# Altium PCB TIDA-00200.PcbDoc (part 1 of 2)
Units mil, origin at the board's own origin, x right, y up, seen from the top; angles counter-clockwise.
Board outline 5000 x 4400 mil, 2 copper layers (Top Layer, Bottom Layer), stack 62 mil thick; 122 components, 56 nets, 288 pads, 55 vias.
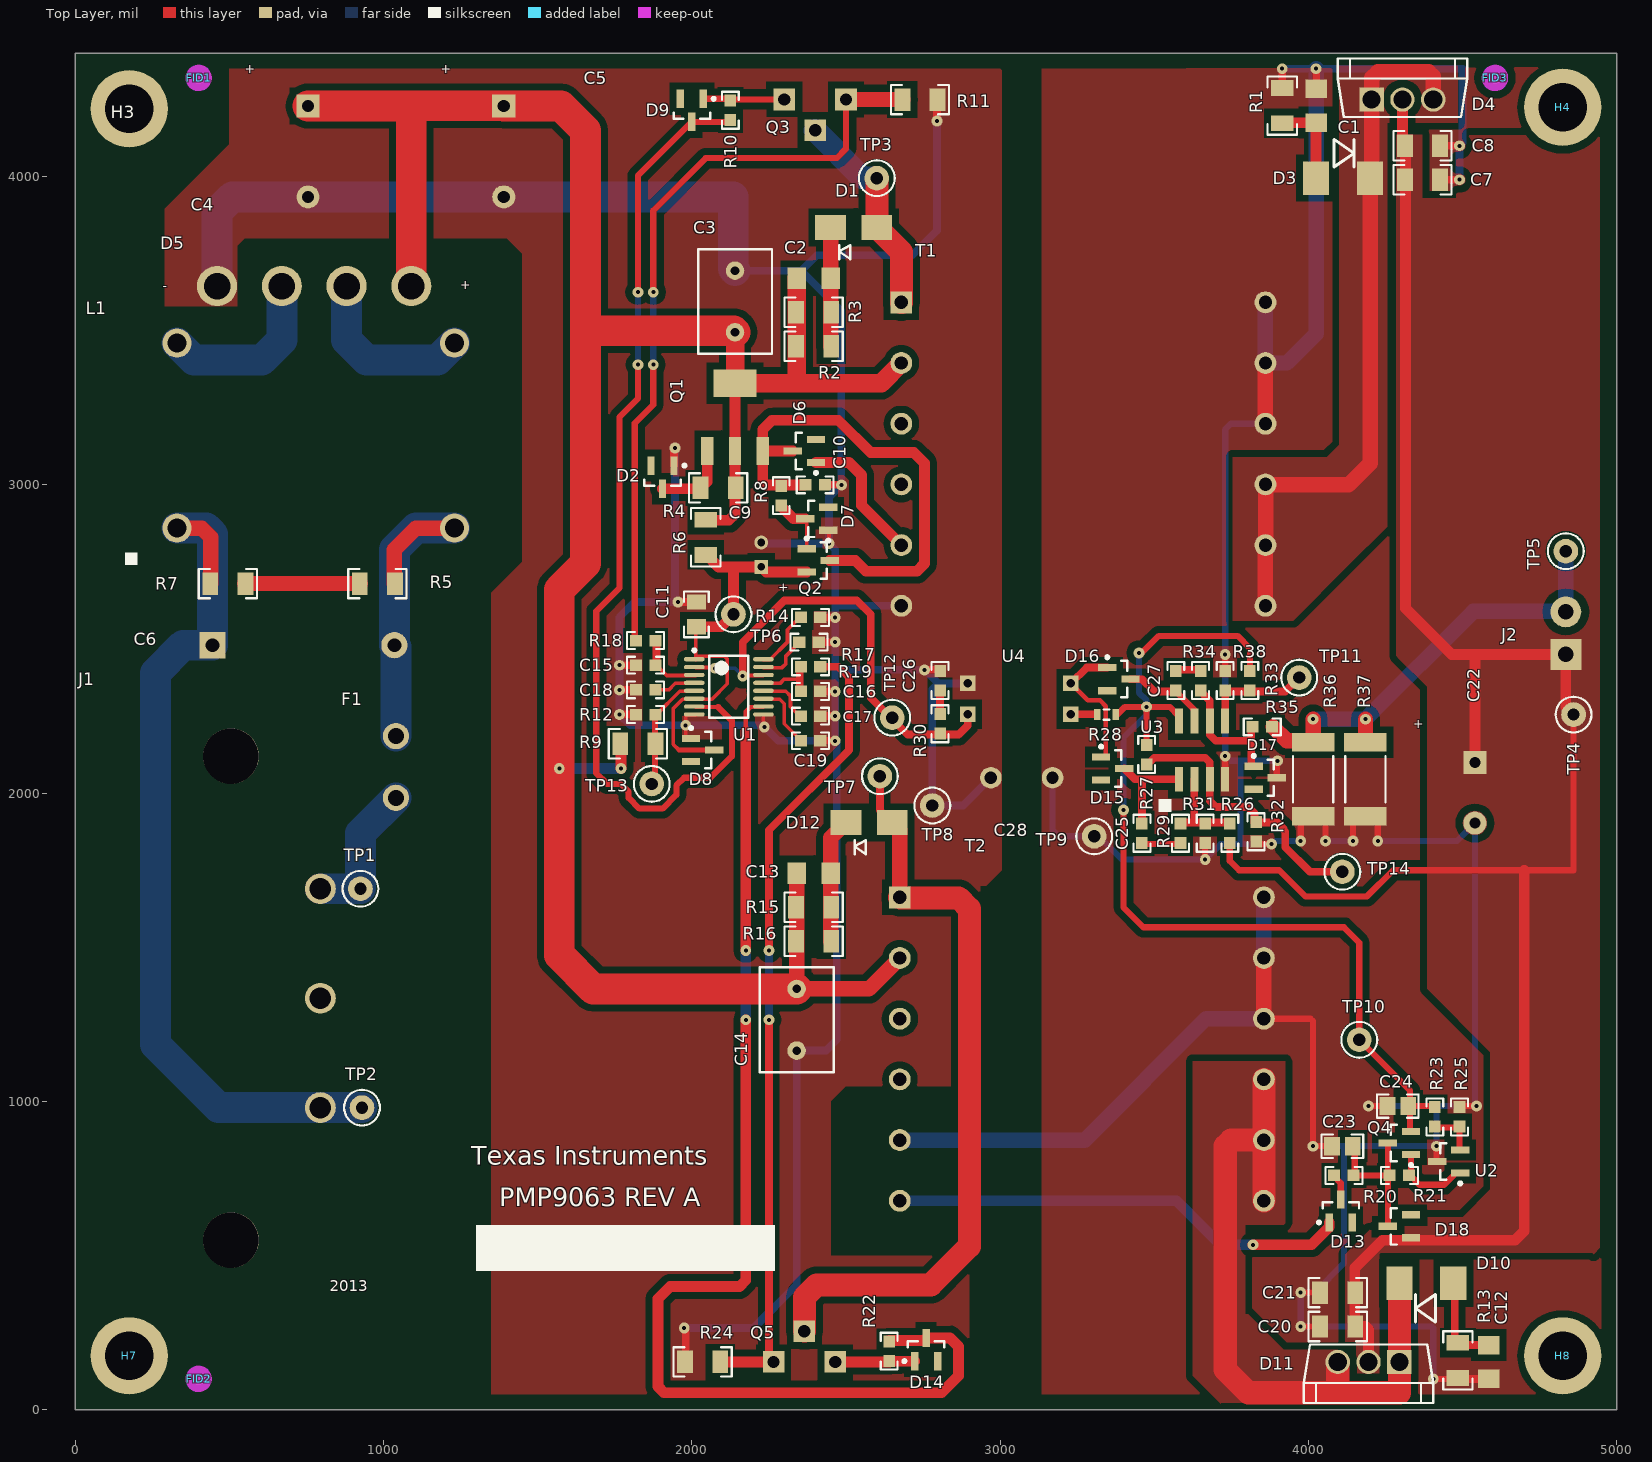
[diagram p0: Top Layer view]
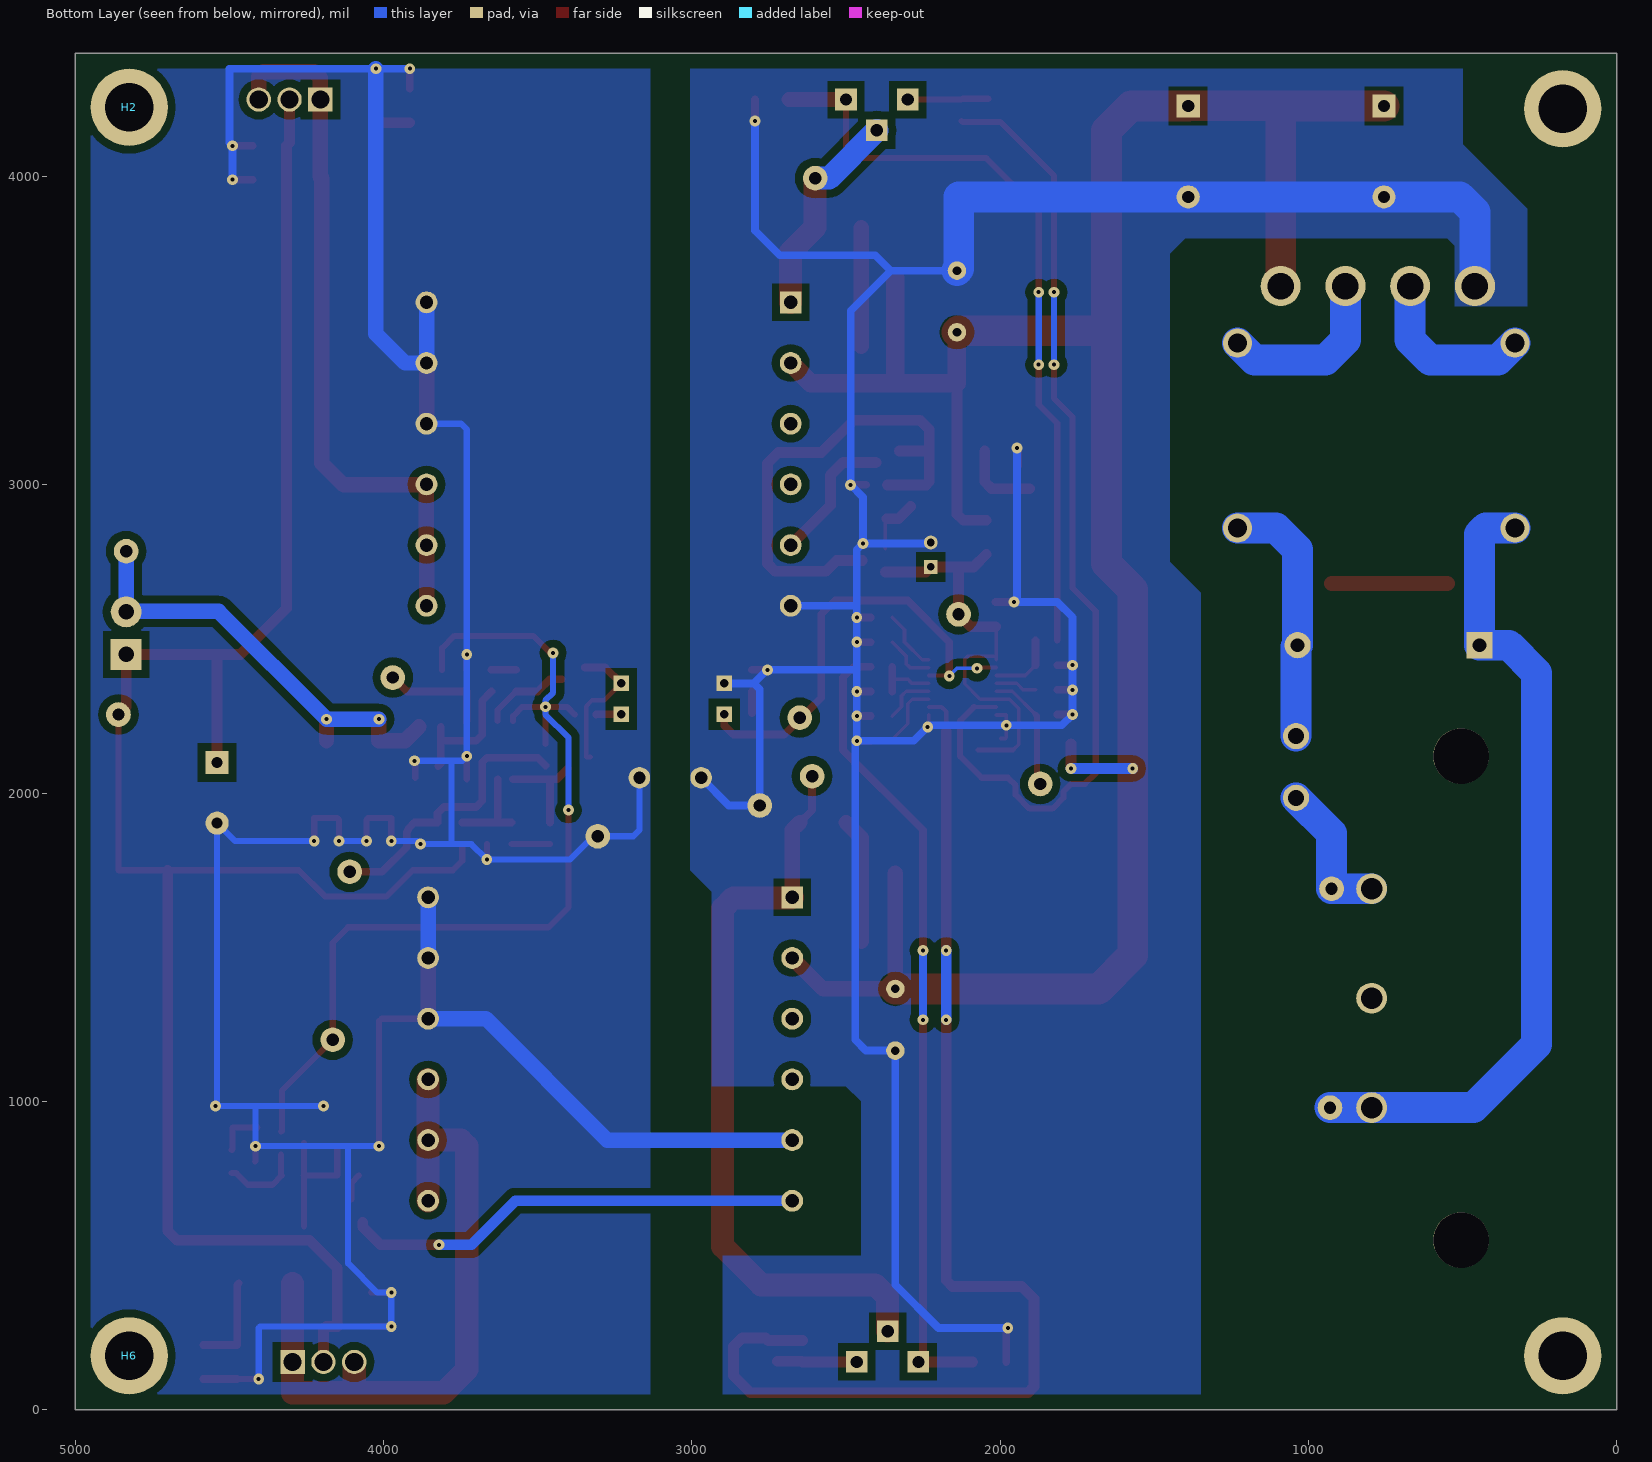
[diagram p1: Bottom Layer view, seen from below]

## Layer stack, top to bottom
Top Layer: signal copper 1.4
Dielectric: core 59.2, FR-4, Dk 4.8
Bottom Layer: signal copper 1.4

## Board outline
0,0 0,4400 5000,4400 5000,0

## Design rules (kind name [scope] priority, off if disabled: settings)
AcuteAngle [All] p1: minimum=4.50000000000000E+0001 checktracksonly=FALSE
AssemblyTestPointUsage [All] p1: valid=2
Clearance Clearance_BoardEdge_MountingHoles [OnCopper and InComponentClass('Mounting Holes') vs IsKeepOut] p1: gap=25
Clearance Clearance_BoardEdge_Poly [OnCopper and InPoly vs IsKeepOut] p2: gap=25
Clearance Clearance_BoardEdge [OnCopper and Not InComponentClass('Logo') and not InComponentClass('FiducialMark') and not InRegion(1000,500,4000,800) and Not IsKeepout vs IsKeepOut] p3: gap=25
Clearance Clearance_Poly [InPolygon] p4: gap=23
Clearance [All] p5: gap=8
ComponentClearance ComponentClearance_Logo [InComponentClass(Logo)] p1: gap=5 collisioncheckmode=3 verticalgap=5 showdistances=FALSE
ComponentClearance ComponentClearance_ScrewToNut [(HasFootprint('NY PMS 440 0025 PH')) vs (HasFootprint('Keystone_1902C'))] p2: gap=5 collisioncheckmode=3 verticalgap=5 showdistances=FALSE
ComponentClearance ComponentClearance_MountingHoles [InComponentClass('Mounting Holes')] p3: gap=5 collisioncheckmode=3 verticalgap=100000 showdistances=FALSE
ComponentClearance ComponentClearance_SmallPassives [HasFootprint('0201*') or HasFootprint('0402*') or HasFootprint('0508') or HasFootprint('0603*') or HasFootprint('0612') or HasFootprint('0805*') or HasFootprint('0815*') or HasFootprint('0830*') or HasFootprint('1206*') or HasFootprint('1210*') or HasFootprint('1808*') or HasFootprint('1812*') or HasFootprint('1825*') or HasFootprint('2010*') or HasFootprint('2220*') or HasFootprint('2225*') or HasFootprint('2512*') or HasFootprint('2728*') or HasFootprint('3518*') vs HasFootprint('0201*') or HasFootprint('0402*') or HasFootprint('0508') or HasFootprint('0603*') or HasFootprint('0612') or HasFootprint('0805*') or HasFootprint('0815*') or HasFootprint('0830*') or HasFootprint('1206*') or HasFootprint('1210*') or HasFootprint('1808*') or HasFootprint('1812*') or HasFootprint('1825*') or HasFootprint('2010*') or HasFootprint('2220*') or HasFootprint('2225*') or HasFootprint('2512*') or HasFootprint('2728*') or HasFootprint('3518*')] p4: gap=5 collisioncheckmode=3 verticalgap=5 showdistances=FALSE
ComponentClearance ComponentClearance_THtoSMT [IsThruComponent vs IsSMTComponent] p5: gap=0 collisioncheckmode=3 verticalgap=100000 showdistances=FALSE
ComponentClearance ComponentClearance_THtoTH [IsThruComponent vs IsThruComponent] p6: gap=0 collisioncheckmode=3 verticalgap=100000 showdistances=FALSE
ComponentClearance [All] p7: gap=0.1 collisioncheckmode=3 verticalgap=0 showdistances=FALSE
DiffPairsRouting [All] p1: maxlimit=100 minlimit=10 mostfreqgap=10 maxuncoupledlength=1000
FabricationTestPointUsage TestPointUsage [All] p1: valid=2 allowmultiple=FALSE
FabricationTestpoint Testpoint [All] p1: side=3 testpointundercomponent=TRUE minsize=40 maxsize=100 preferedsize=60 minholesize=0 maxholesize=40 preferedholesize=32 testpointgrid=1 allowsidetop=TRUE allowsidebottom=TRUE usegrid=TRUE gridtolerance=0.01
FanoutControl Fanout_LCC [IsLCC] p1: bgadir=Out bgaviamode=Centered fanoutstyle=Auto fanoutdirection=Alternating viagrid=1 // Fanout_LCC (Default Rule)
FanoutControl Fanout_BGA [IsBGA] p2: bgadir=Out bgaviamode=Centered fanoutstyle=Auto fanoutdirection=Alternating viagrid=1 // Fanout_BGA (Default Rule)
FanoutControl Fanout_Default [All] p4: bgadir=Out bgaviamode=Centered fanoutstyle=Auto fanoutdirection=Alternating viagrid=1 // Fanout_Default (Default Rule)
FanoutControl Fanout_Small [(CompPinCount < 5)] p5: bgadir=Out bgaviamode=Centered fanoutstyle=Auto fanoutdirection=OutThenIn viagrid=1 // Fanout_Small (Default Rule)
Height [All] p1: minheight=0 maxheight=1500 prefheight=500
HoleSize [All] p1: absolutevalues=TRUE maxlimit=251 minlimit=8 maxpercent=80.000 minpercent=20.000
MinimumAnnularRing [All] p1: minimumring=9
MinimumSolderMaskSliver MinimumSolderMaskSliver_Logo [InComponentClass('Logo') vs InComponentClass('Logo')] p1: minsoldermaskwidth=0.7
MinimumSolderMaskSliver [All] p2: minsoldermaskwidth=3
PlaneClearance [All] p1: clearance=15
PlaneConnect [All] p1: planeconnectstyle=Direct reliefexpansion=10 reliefentries=4 reliefconductorwidth=10 reliefairgap=10
PolygonConnect [All] p1: connectstyle=Direct reliefconductorwidth=10 reliefentries=4 polygonreliefangle="90 Angle" airgapwidth=10
RoutingCorners [All] p1: cornerstyle=45-Degree minsetback=1 maxsetback=5
RoutingVias [All] p1: holewidth=13 width=35 viastyle="Through Hole" minholewidth=13 minwidth=35 maxholewidth=13 maxwidth=35
SMDToCorner [All] p1: distance=10000
SilkToSilkClearance [All] p1: silktosilkclearance=1
SilkscreenOverComponentPads [All] p1: minsilkscreentomaskgap=1
SolderMaskExpansion [All] p1: expansion=2
Width [All] p1: maxlimit=100 minlimit=6 preferedwidth=20 checkconnectedcopper=TRUE
11 further rules are at their usual default settings.

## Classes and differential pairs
component class PMP9063A: C1 C2 C3 C4 C5 C6 C7 C8 C9 C10 C11 C12 C13 C14 C15 C16 C17 C18 C19 C20 C21 C22 C23 C24 C25 C26 C27 C28 D1 D2 D3 D4 D5 D6 D7 D8 D9 D10 D11 D12 D13 D14 D15 D16 D17 D18 F1 J1 J2 L1 Q1 Q2 Q3 Q4 Q5 R1 R2 R3 R4 R5 R6 R7 R8 R9 R10 R11 R12 R13 R14 R15 R16 R17 R18 R19 R20 R21 R22 R23 R24 R25 R26 R27 R28 R29 R30 R31 R32 R33 R34 R35 R36 R37 R38 T1 T2 TP1 TP2 TP3 TP4 TP5 TP6 TP7 TP8 TP9 TP10 TP11 TP12 TP13 TP14 U1 U2 U3 U4
component class FiducialMark: FID1 FID2 FID3
component class Hardware_ANSI-B: FID1 FID2 FID3 H2 H3 H4 H6 H7 H8
component class "Mounting Holes": H3 H4 H7 H8

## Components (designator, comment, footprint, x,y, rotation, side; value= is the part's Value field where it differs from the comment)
C1 "C1206" C1206 4025,4230 r270 top
C2 "C1206" C1206 2395,3670 r180 top
C3 "CAP_ECQ-E2104KB" CAP_ECQ-E2104KB 2140,3695 r270 top
C4 "EEUEB2D151" CAP_ZL-7.5X14.5MM 755,4080 r0 top
C5 "EEUEB2D151" CAP_ZL-7.5X14.5MM 1390,4080 r0 top
C6 "CAP_B81130-C1104-MXXX" CAP_590PITCH 445,2480 r0 top
C7 "C1206C105K3RACTU" 1206 4370,3990 r180 top
C8 "C1206C105K3RACTU" 1206 4370,4100 r180 top
C9 "CAP_ZL_5MM_SERIES" CAP_ZL-5MM 2225,2775 r180 top
C10 "C0603C104K5RACTU" 0603 2400,3000 r180 top
C11 "C0805C105K4RACTU" 0805_HV 2015,2580 r270 top
C12 "C1206" C1206 4585,155 r270 top
C13 "C1206" C1206 2395,1740 r180 top
C14 "CAP_ECQ-E2104KB" CAP_ECQ-E2104KB 2340,1165 r90 top
C15 "C0603C101J5GACTU" 0603 1850,2415 r0 top
C16 "C0603C101J5GACTU" 0603 2385,2330 r180 top
C17 "C0603C102K5RACTU" 0603 2385,2250 r180 top
C18 "C0603C102K5RACTU" 0603 1850,2335 r0 top
C19 "C0603C104K5RACTU" 0603 2385,2170 r180 top
C20 "C1206C105K3RACTU" 1206 4095,270 r0 top
C21 "C1206C105K3RACTU" 1206 4095,380 r0 top
C22 "CAP_ZL_12.5MM_SERIES" CAP_ZL-5X12.5MM 4540,2000 r0 top
C23 "C2012X7R1E105K" 0805 4110,855 r0 top
C24 "C0805C104K3RACTU" 0805 4290,985 r0 top
C25 "C0603C104K5RACTU" 0603 3460,1870 r90 top
C26 "C0603C103K5RACTU" 0603 2805,2365 r270 top
C27 "C0603C104K5RACTU" 0603 3570,2365 r270 top
C28 "CAP_ECKNVS-9MMDIA" CAP-200MIL 2970,2050 r0 top
D1 "D-MURA160T3G" 403D 2525,3835 r0 top
D2 "D-MMBZ52XXBLT1_SERIES" SOT-23 1905,3025 r270 top
D3 "D-MURA120T3" 403A 4115,3995 r180 top
D4 "NTST40120CTG" TO-262 4205,4250 r0 top
D5 "D-BRIDGE_GBU_SERIES" BRIDGE-INLINE-210-C 1090,3645 r180 top
D6 "D-BAS16" SOT-23 2365,3110 r180 top
D7 "D-MMBZ52XXBLT1_SERIES" SOT-23 2405,2890 r180 top
D8 "D-MMBZ52XXBLT1_SERIES" SOT-23 2035,2140 r0 top
D9 "D-BAS16" SOT-23 2000,4215 r270 top
D10 "D-MURA120T3" 403A 4380,410 r0 top
D11 "NTST40120CTG" TO-262 4295,155 r180 top
D12 "D-MURA160T3G" 403D 2575,1905 r0 top
D13 "D-BAS16" SOT-23 4105,645 r90 top
D14 "D-BAS16" SOT-23 2760,195 r90 top
D15 "D-BAS16" SOT-23 3365,2080 r0 top
D16 "D-BAS16" SOT-23 3385,2370 r0 top
D17 "D-BAS16" SOT-23 3860,2050 r0 top
D18 "D-BAS16" SOT-23 4295,595 r180 top
F1 "FUSE_TR5_SERIES" FUSE_370_ 1040,1985 r90 top
FID1 "Fiducial" Fiducial10-20 400,4320 r0 top
FID2 "Fiducial" Fiducial10-20 400,100 r0 top
FID3 "Fiducial" Fiducial10-20 4605,4320 r0 top
H2 "1902C" Keystone_1902C 4825,4225 r180 bottom locked
H3 "NY PMS 440 0025 PH" "NY PMS 440 0025 PH" 175,4220 r90 top
H4 "NY PMS 440 0025 PH" "NY PMS 440 0025 PH" 4825,4225 r0 top locked
H6 "1902C" Keystone_1902C 4825,175 r180 bottom locked
H7 "NY PMS 440 0025 PH" "NY PMS 440 0025 PH" 175,175 r0 top
H8 "NY PMS 440 0025 PH" "NY PMS 440 0025 PH" 4825,175 r0 top locked
J1 "CONN_AC_HP-TYPE" CONN_AC_HP-TYPE 400,1335 r90 top
J2 "TBLK_6A_2X3.5MM" TB_2X3.5MM 4835,2450 r90 top
L1 "IND_GVTM1_SERIES" IND_COUPLED_1400_X_820 780,3160 r0 top
Q1 "TR-FZT649" S0T223 2140,3220 r0 top
Q2 "TR-MMBT3904LT1G" SOT-23 2410,2755 r0 top
Q3 "TR_NFET_TO-220V" TO-220V 2300,4250 r0 top
Q4 "TR-MMBT3904LT1G" SOT-23 4295,865 r180 top
Q5 "TR_NFET_TO-220V" TO-220V 2465,155 r180 top
R1 "CRCW120620K0JNEA" 1206 3915,4230 r90 top
R2 "CRCW1206200KJNEA" 1206 2395,3450 r0 top
R3 "CRCW1206200KJNEA" 1206 2395,3560 r0 top
R4 "CRCW1206100KJNEA" 1206 2085,2990 r180 top
R5 "CRCW1206200KJNEA" 1206 980,2680 r180 top
R6 "CRCW1206100KJNEA" 1206 2045,2830 r270 top
R7 "CRCW1206200KJNEA" 1206 495,2680 r180 top
R8 "CRCW060320K0JNEA" 0603 2290,2965 r90 top
R9 "CRCW12061M00FKEA" 1206 1825,2160 r0 top
R10 "CRCW060310R0FKEA" 0603 2125,4215 r90 top
R11 "ERJ-8RSJR15V" 1206 2740,4250 r0 top
R12 "CRCW060312K4FKEA" 0603 1850,2255 r0 top
R13 "CRCW120620K0JNEA" 1206 4485,160 r90 top
R14 "CRCW060386K6FKEA" 0603 2385,2570 r180 top
R15 "CRCW1206200KJNEA" 1206 2395,1630 r0 top
R16 "CRCW1206200KJNEA" 1206 2395,1520 r0 top
R17 "CRCW0603200KJNEA" 0603 2380,2490 r180 top
R18 "CRCW06032K49FKEA" 0603 1850,2495 r0 top
R19 "CRCW06032K49FKEA" 0603 2385,2410 r180 top
R20 "CRCW060310R0FKEA" 0603 4115,760 r0 top
R21 "CRCW06034K99FKEA" 0603 4295,760 r0 top
R22 "CRCW060310R0FKEA" 0603 2640,190 r270 top
R23 "CRCW06037K50JNEA" 0603 4410,950 r270 top
R24 "ERJ-8RSJR15V" 1206 2035,155 r180 top
R25 "CRCW06032K49FKEA" 0603 4490,950 r90 top
R26 "CRCW060318K7FKEA" 0603 3745,1870 r90 top
R27 "CRCW06037K50JNEA" 0603 3475,2125 r270 top
R28 "CRCW06032K49FKEA" 0603S 3345,2255 r180 top
R29 "CRCW060320K0JNEA" 0603 3585,1870 r90 top
R30 "CRCW06031K00JNEA" 0603 2805,2225 r270 top
R31 "CRCW06032K49FKEA" 0603 3665,1870 r270 top
R32 "CRCW06032K49FKEA" 0603 3830,1875 r270 top
R33 "CRCW060321K0FKEA" 0603 3810,2365 r270 top
R34 "CRCW06031K00JNEA" 0603 3650,2365 r270 top
R35 "CRCW06031K00JNEA" 0603 3850,2215 r0 top
R36 "WSL2512R0100FEA" 2512M 4015,2045 r270 top
R37 "WSL2512R0100FEA" 2512M 4185,2045 r270 top
R38 "CRCW0603100RJNEA" 0603 3730,2365 r90 top
T1 "G135067LF" GCI_G135067LF-rev3 3270,3100 r0 top
T2 "G135067LF" GCI_G135067LF-rev3 3265,1170 r0 top
TP1 "5000" Keystone5000 925,1690 r0 top
TP2 "5000" Keystone5000 930,980 r0 top
TP3 "5000" Keystone5000 2600,3995 r0 top
TP4 "5000" Keystone5000 4860,2255 r0 top
TP5 "5001" Keystone5001 4835,2785 r0 top
TP6 "5000" Keystone5000 2135,2580 r0 top
TP7 "5000" Keystone5000 2610,2055 r0 top
TP8 "5001" Keystone5001 2780,1960 r0 top
TP9 "5001" Keystone5001 3305,1860 r0 top
TP10 "5000" Keystone5000 4165,1200 r90 top
TP11 "5000" Keystone5000 3970,2375 r90 top
TP12 "5000" Keystone5000 2650,2245 r90 top
TP13 "5000" Keystone5000 1870,2030 r90 top
TP14 "5000" Keystone5000 4110,1745 r90 top
U1 "LM5032MTC/NOPB" MTC16_N 2120,2345 r0 top
U2 "TL431AIDBZ" SOT-23 4455,805 r180 top
U3 "TLC272CD" SO8 3655,2140 r90 top
U4 "_H11A817" H11_OPTO_4P 3230,2255 r180 top

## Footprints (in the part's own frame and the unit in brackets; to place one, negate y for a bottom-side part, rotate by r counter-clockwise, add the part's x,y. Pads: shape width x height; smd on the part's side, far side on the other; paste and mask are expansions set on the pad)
403A [mil]
  rect 85x108 smd: 1(-85,0) 2(90,0)
  silkscreen extent -33,-126 33,-36
403D [mil]
  rect 100x80 smd: 1(-75,0) 2(75,0)
  silkscreen extent -47,-102 -12,-57
0603 [mm] "0603 from SM-752 data"
  rect 1x0.95 smd: 1(-0.8,0) 2(0.8,0)
  silkscreen extent -1.52,-0.69 1.52,0.69, body extent -0.87,-0.47 0.87,0.47, height 0.85
0603S [mil]
  rect 20x35 smd: 1(-30,0) 2(30,0)
  silkscreen extent -10,-17 10,17, body extent -34,-19 34,19, height 33
0805 [mm] "0805 from SM-752 data"
  rect 1.3x1.5 smd: 1(-0.85,0) 2(0.85,0)
  silkscreen extent -1.72,-0.97 1.72,0.97, body extent -1.1,-0.72 1.1,0.72, height 1.1
0805_HV [mil] "0805 with 30mil clearance between pads"
  rect 50x63 smd: 1(-40,0) 2(40,0)
  silkscreen extent -74,-40 74,40, body extent -43,-29 43,29, height 43
1206 [mm] "1206 from SM-752 data"
  rect 1.3x1.85 smd: 1(-1.45,0) 2(1.45,0)
  silkscreen extent -2.4,-1.21 2.4,1.21, body extent -1.7,-0.9 1.7,0.9, height 1.35
2512M [mm] "Chip Resistor, Body 6.3x3.2mm, IPC Low Density"
  rect 1.5x3.5 smd: 1(-3.05,0) 2(3.05,0)
  silkscreen extent -1.9,-1.65 1.9,1.65, body extent -3.22,-1.67 3.22,1.67, height 0.71
BRIDGE-INLINE-210-C [mil]
  round 130 hole 86: 1(0,0) 2(210,0) 3(420,0) 4(630,0)
C1206 [mil]
  rect 60x70 smd: 1(-55,0) 2(55,0)
CAP-200MIL [mil]
  round 70 hole 40 mask+5: 1(0,0) 2(200,0)
CAP_590PITCH [mil]
  rect 85x85 hole 45 mask+5: 1(0,0)
  round 85 hole 45 mask+5: 2(590,0)
CAP_ECQ-E2104KB [mil]
  round 60 hole 28: 1(0,0) 2(200,0)
  silkscreen extent -70,-120 270,120
CAP_ZL-5MM [mil]
  rect 45x45 hole 25: 1(0,41)
  round 45 hole 25: 2(0,-38)
CAP_ZL-5X12.5MM [mil]
  rect 75x75 hole 36: 1(0,100)
  round 75 hole 36: 2(0,-97)
CAP_ZL-7.5X14.5MM [mil]
  rect 75x75 hole 40: 1(0,149)
  round 75 hole 40: 2(0,-146)
CONN_AC_HP-TYPE [mil]
  round 100 hole 70: 1(355,-395) 2(-355,-395) 3(0,-395)
  round 180 hole 180 unplated: 4(-785,-105) 5(785,-105)
Fiducial10-20 [mm]
  round 1 smd paste-0.5 mask+0.5: 1(0,0)
  Top Layer keep-out circle w1.178: c0,0 r0.5
FUSE_370_ [mil]
  round 85 hole 52: 1(0,0) 2(200,0)
GCI_G135067LF-rev3 [mm] "GCI Technologies"
  rect 1.8x1.8 hole 1.1: 1(-15,12.5)
  round 1.8 hole 1.1: 2(-15,7.5) 3(-15,2.5) 4(-15,-2.5) 5(-15,-7.5) 6(-15,-12.5) 7(15,-12.5) 8(15,-7.5) 9(15,-2.5) 10(15,2.5) 11(15,7.5) 12(15,12.5)
  body extent -19.25,-15.75 19.25,15.75, height 26.5
H11_OPTO_4P [mil]
  rect 50x50 hole 28: 1(0.5,-1) 2(0.5,-101) 3(335.5,-101) 4(335.5,-1)
IND_COUPLED_1400_X_820 [mil]
  round 95 hole 62: 1(-450,-300) 2(450,-300) 3(450,300) 4(-450,300)
  silkscreen extent -618,-420 -579,-380
Keystone5000 [mil] "For Keystone 500x miniature loop terminals"
  round 80 hole 40: 1(0,0)
  silkscreen extent -58,-58 58,58, body extent -49,-49 49,49, height 182
Keystone5001 [mil] "For Keystone 500x miniature loop terminals"
  round 80 hole 40: 1(0,0)
  silkscreen extent -58,-58 58,58, body extent -49,-49 49,49, height 182
Keystone_1902C [mil] "Hex Standoff, 4-40 threaded, nylon"
  body extent -145,-126 146,126, height 501
MTC16_N [mm] "TSOP, 16-Leads, Body 5x4.4mm, Pitch 0.65mm, IPC Medium Density"
  oval 1.7x0.35 smd: 1(-2.85,2.275) 2(-2.85,1.625) 3(-2.85,0.975) 4(-2.85,0.325) 5(-2.85,-0.325) 6(-2.85,-0.975) 7(-2.85,-1.625) 8(-2.85,-2.275) 9(2.85,-2.275) 10(2.85,-1.625) 11(2.85,-0.975) 12(2.85,-0.325) 13(2.85,0.325) 14(2.85,0.975) 15(2.85,1.625) 16(2.85,2.275)
  silkscreen extent -2.97,-2.55 1.6,3.12, body extent -2.25,-2.55 2.25,2.55, height 1.1
"NY PMS 440 0025 PH" [mil] "4-40 nylon screw and mounting hole"
  round 250 hole 156: 1(0,0)
  body extent -130,-130 130,130, height 106
S0T223 [mil]
  rect 40x90 smd: 1(-90,-110) 2(0,-110) 3(90,-110)
  rect 140x90 smd: 4(0,110)
SO8 [mil]
  rect 80x26 smd: 1(-95,75) 2(-95,25) 3(-95,-25) 4(-95,-75) 5(94,-75) 6(94,-25) 7(94,25) 8(94,75)
  silkscreen extent -200,100 -160,140
SOT-23 [mm] "SOT23, 3-Leads, Body 2.9x1.3mm, Pitch 0.95mm, Lead Span 2.5mm, IPC Medium Density"
  rect 1.5x0.6 smd: 1(-0.95,0.95) 2(-0.95,-0.95) 3(0.95,0)
  silkscreen extent -1.07,-1.5 0.7,1.93, body extent -1.16,-1.45 1.21,1.45, height 1
TB_2X3.5MM [mil]
  rect 100x100 hole 50: 1(0,0)
  round 100 hole 50: 2(138,0)
TO-220V [mil]
  rect 70x70 hole 40: 1(0,0) 2(100,-100) 3(200,0)
TO-262 [mm]
  rect 2x2 hole 1.5: 1(0,0)
  round 2 hole 1.5: 2(2.54,0) 3(5.08,0)
  silkscreen extent -2.79,-1.44 7.88,3.39, body extent -2.79,-1.44 7.88,3.39, height 15.36

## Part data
C1 C12: "Capacitor, Ceramic, 250V, [temp],  [tol]"
C2 C13: "Capacitor, Ceramic Chip, 250V, ±10%"
C3 C14: "Capacitor, Polyester, 400V, 10%"
C4 C5: library part CAP_ZL_16MM_SERIES, "Capacitor, multi pattern, TH 0.080 to 0.200"
C6: "Capacitor, Leaded, 0.10 uF, 275 VAC, X2"
C7 C8 C20 C21: "CAP, CERM, 1uF, 25V, +/-10%, X7R, 1206"
C9: "Capacitor, Aluminum Electrolytic, vvV"
C10 C19 C25 C27: "CAP, CERM, 0.1uF, 50V, +/-10%, X7R, 0603"
C11: "CAP, CERM, 1uF, 16V, +/-10%, X7R, 0805"
C15 C16: "CAP, CERM, 100pF, 50V, +/-5%, C0G/NP0, 0603"
C17 C18: "CAP, CERM, 1000pF, 50V, +/-10%, X7R, 0603"
C22: "Capacitor, multi pattern, SM 1210 to E case + F THole"
C23: "CAP, CERM, 1uF, 25V, +/-10%, X7R, 0805"
C24: "CAP, CERM, 0.1uF, 25V, +/-10%, X7R, 0805"
C26: "CAP, CERM, 0.01uF, 50V, +/-10%, X7R, 0603"
C28: "Capacitor, Ceramic Disc, 250WV, 4700pF, Y5U ±20%"
D1 D12: "Rectifier, SMD Ultrafast  Power, 600V 1A"
D2 D7: "Diode, Zener, 12V, yy-mA"
D3 D10: "Diode, UltraFast Rectifier, 1-A, 200-V"
D4 D11: library part VS-48CTQ060-1PbF, "Diode, Schottky, 60V, 20A, TH"
D5: "Diode, Bridge Rectifier, 6 A, 400V"
D6 D9 D13 D14 D15 D16 D17 D18: "Diode, Switching, 200mA, 100V, 300mW"
D8: "Diode, Zener, 15V, yy-mA"
F1: "Fuse, TR5 Series, 6 slow, 250V"
FID1 FID2 FID3: "Fiducial mark.  There is nothing to buy or mount."
H2 H6: "Standoff, Hex, 0.5\"L #4-40 Nylon"
H3 H4 H7 H8: "Machine Screw, Round, #4-40 x 1/4, Nylon, Philips panhead"
J1: "Connector, AC Board mount, 9mm"
J2: "Terminal Block, 2-pin, 6-A, 3.5mm"
L1: "Inductor, Common Mode Choke,"
Q1: "Trans, NPN Midium Power, 300V 3A"
Q2 Q4: "Trans, NPN, xx-V, yy-mA, zz-W"
Q3 Q5: "MOSFET, N-ch, 500-V, yy-A, 85-milliOhms"
R1 R13: "RES, 20k ohm, 5%, 0.25W, 1206"
R2 R3 R5 R7 R15 R16: "RES, 200k ohm, 5%, 0.25W, 1206"
R4 R6: "RES, 100k ohm, 5%, 0.25W, 1206"
R8 R29: "RES, 20k ohm, 5%, 0.1W, 0603"
R9: "RES, 1.00Meg ohm, 1%, 0.25W, 1206"
R10 R20 R22: "RES, 10.0 ohm, 1%, 0.1W, 0603"
R11 R24: "RES, 0.15 ohm, 5%, 0.25W, 1206"
R12: "RES, 12.4k ohm, 1%, 0.1W, 0603"
R14: "RES, 86.6k ohm, 1%, 0.1W, 0603"
R17: "RES, 200k ohm, 5%, 0.1W, 0603"
R18 R19 R25 R28 R31 R32: "RES, 2.49k ohm, 1%, 0.1W, 0603"
R21: "RES, 4.99k ohm, 1%, 0.1W, 0603"
R23 R27: "RES, 7.5k ohm, 5%, 0.1W, 0603"
R26: "RES, 18.7k ohm, 1%, 0.1W, 0603"
R30 R34 R35: "RES, 1.0k ohm, 5%, 0.1W, 0603"
R33: "RES, 21.0k ohm, 1%, 0.1W, 0603"
R36 R37: "RES, 0.01 ohm, 1%, 1W, 2512"
R38: "RES, 100 ohm, 5%, 0.1W, 0603"
T1 T2: "Transformer, Flyback, 500uH, TH"
TP1 TP2 TP3 TP4 TP6 TP7 TP10 TP11 TP12 TP13 TP14: "Test Point, Miniature, Red, TH"
TP5 TP8 TP9: "Test Point, Miniature, Black, TH"
U1: "High Voltage Dual Interleaved Current Mode Controller, 16-pin TSSOP, Pb-Free"
U2: "IC, Precision Adjustable Shunt Regulator"
U3: "IC, Precision Dual Operational Amplifiers"
U4: "IC, Optocoupler, 5300-V, 80-160% CTR"

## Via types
v1: diameter 35, hole 13, Top Layer to Bottom Layer, 55 vias

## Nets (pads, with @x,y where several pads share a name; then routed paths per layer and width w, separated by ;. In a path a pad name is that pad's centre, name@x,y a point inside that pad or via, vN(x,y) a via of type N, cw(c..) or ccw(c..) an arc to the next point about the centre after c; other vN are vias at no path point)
10V: C24.2 Q4.2 R23.1 R27.1 R28.1 R33.1 TP10.1 U3.8 | length 3269.1
  Top Layer w20: R28.1@3380,2255 3405,2280 v1(3475,2280) ; v1(3400,1945) 3400,1630 3465,1565 4115,1565 4165,1515 TP10.1@4165,1200 4330,1035 C24.2@4330,985 ; v1(3450,2455) 3460,2455 3515,2510 3770,2510 3810,2470 R33.1@3810,2400 ; R27.1@3475,2160 v1(3475,2280) ; U3.8@3580,2234 3580,2250 3550,2280 v1(3475,2280) ; Q4.2@4332.4,902.4 4330,904.8 C24.2@4330,985 ; R23.1@4410,985 C24.2@4330,985
  Bottom Layer w20: v1(3400,1945) 3400,2180 3475,2255 v1(3475,2280) 3475,2301.01 3450,2326.01 v1(3450,2455)
CS1: Q3.3 R11.1 R18.1 | length 2472.7
  Top Layer w20: R18.1@1815,2495 1815,3200 1875,3260 v1(1875,3390) ; v1(1875,3625) 1875,3890 2045,4060 2470,4060 2500,4090 Q3.3@2500,4250
  Top Layer w50: Q3.3@2500,4250 R11.1@2685,4250
  Bottom Layer w20: v1(1875,3390) v1(1875,3625)
CS2: Q5.3 R19.1 R24.1 | length 2602.2
  Top Layer w25: Q5.3@2250,160 v1(2250,1265) ; v1(2250,1490) 2250,1880 2510,2140 2510,2375 2475,2410 R19.1@2420,2410
  Top Layer w35: R24.1@2090,155 Q5.3@2265,155
  Bottom Layer w25: v1(2250,1265) v1(2250,1490)
NetC1_2: C1.2 D3.2 R1.1 | length 290
  Top Layer w35: R1.1@3915,4175 C1.2@4025,4175 D3.2@4025,3995
NetC2_1: C2.1 D1.1 R2.2 R3.2 | length 385
  Top Layer w50: R2.2@2450,3450 2450,3560 C2.1@2450,3670 D1.1@2450,3835
NetC6_1: C6.1 J1.2 L1.1 R7.2 TP2.1 | length 2937.9
  Top Layer w50: L1.1@330,2860 410,2860 440,2830 R7.2@440,2680
  Bottom Layer w100: L1.1@330,2860 425,2860 445,2840 C6.1@445,2480 350,2480 260,2390 260,1185 465,980 J1.2@795,980 TP2.1@930,980
NetC6_2: C6.2 F1.2 L1.2 R5.1 | length 1165.1
  Top Layer w50: R5.1@1035,2680 1035,2790 1105,2860 L1.2@1230,2860
  Bottom Layer w100: F1.2@1040,2185 1040,2475 C6.2@1035,2480 1035,2790 1105,2860 L1.2@1230,2860
NetC7_2: C7.2 C8.2 C20.2 C21.2 C22.1 D4.2 D11.2 D18.1 J2.1 R26.1 TP4.1 | length 6672.2
  Top Layer w20: R26.1@3745,1835 3745,1780 3775,1750 3905,1750 3990,1665 4190,1665 4275,1750 4700,1750 4860,1750 TP4.1@4860,2255 ; D18.1@4330,549.71 4330,550 4330,555.2 D18.1@4332.4,557.6
  Top Layer w35: D11.2@4195,155 4195,260 4185,270 4150,270 4150,380 4150,460 4240,550 4330,550 4670,550 4700,580 4700,1750 ; D4.2@4305,4250 4305,4110 4315,4100 4315,3990 4315,2600 4465,2450 4540,2450 ; C22.1@4540,2100 4540,2450 ; TP4.1@4860,2255 4835,2280 J2.1@4835,2450 4540,2450
NetC9_1: C9.1 C11.2 D8.3 Q2.2 R6.2 TP6.1 U1.1 U1.6 | length 1400.8
  Top Layer w12: 1958.23,2140 1940,2158.23 1940,2275 1970,2305 2012.7,2305 2065,2305 2115,2355 2115,2435 2106.01,2443.99 2012.7,2443.99 ; U1.1@2012.7,2433 2012.7,2443.99 ; C11.2@2015,2540 2012.7,2537.7 2012.7,2443.99
  Top Layer w15: 1958.23,2140 D8.3@2072.4,2140
  Top Layer w35: C11.2@2015,2540 2095,2540 TP6.1@2135,2580 2135,2734 ; R6.2@2045,2775 2086,2734 2135,2734 ; Q2.2@2372.6,2717.6 2241.4,2717.6 C9.1@2225,2734 2135,2734
NetC10_2: C10.2 D6.3 Q1.3 Q2.3 R8.2 | length 1659.6
  Top Layer w35: D6.3@2327.6,3110 Q1.3@2230,3110 ; C10.2@2365,3000 2290,3000 2240,3000 2230,3010 Q1.3@2230,3110 ; Q2.3@2447.4,2755 2530,2755 2565,2720 2730,2720 2755,2745 2755,3070 2720,3105 2580,3105 2475,3210 2260,3210 2230,3180 Q1.3@2230,3110
NetC12_1: C12.1 D10.2 R13.2 | length 312.1
  Top Layer w25: D10.2@4470,410 4475,405 4475,210 C12.1@4585,210
NetC13_1: C13.1 D12.1 R15.2 R16.2 | length 405.7
  Top Layer w50: R16.2@2450,1520 2450,1630 C13.1@2450,1740 2450,1855 D12.1@2500,1905
NetC15_2: C15.2 R18.2 U1.3 | length 221.5
  Top Layer w12: C15.2@1885,2415 1918.2,2381.8 U1.3@2012.7,2381.8
  Top Layer w25: C15.2@1885,2415 R18.2@1885,2495
NetC16_2: C16.2 R19.2 U1.13 | length 205.6
  Top Layer w12: U1.13@2231.7,2356.1 2286.1,2356.1 2300,2370 2350,2370 ; 2348.9,2356.1 2350,2355
  Top Layer w25: C16.2@2350,2330 2350,2355 2350,2370 R19.2@2350,2410
NetC17_2: C17.2 U1.12 | length 172.1
  Top Layer w12: U1.12@2231.7,2330.5 2304.5,2330.5 2320,2315 2320,2280 C17.2@2350,2250
NetC18_2: C18.2 U1.4 | length 136.5
  Top Layer w12: C18.2@1885,2335 1925,2335 1946.2,2356.2 U1.4@2012.7,2356.2
NetC19_2: C19.2 U1.11 | length 215.2
  Top Layer w12: U1.11@2231.7,2304.9 2285.1,2304.9 2300,2290 2300,2225 2350,2175 C19.2@2350,2170
NetC23_2: C23.2 D18.3 Q4.3 R20.2 R21.1 | length 478.4
  Top Layer w20: C23.2@4150,855 4150,760 R21.1@4257.6,760 ; D18.3@4257.6,595 R21.1@4257.6,760 ; Q4.3@4257.6,865 R21.1@4257.6,762.4 ; R21.1@4257.6,760 4260,760 R21.1@4257.6,762.4 ; R21.1@4257.6,760 R21.1@4257.6,762.4
NetC25_1: C25.1 R29.1 | length 125
  Top Layer w20: C25.1@3460,1835 R29.1@3585,1835
NetC25_2: C25.2 D15.3 U3.1 | length 332.1
  Top Layer w25: D15.3@3402.4,2080 3437.4,2045 3460,2045 ; C25.2@3460,1905 3460,2045 ; U3.1@3580,2045 3460,2045
NetC26_2: C26.2 R30.1 | length 70
  Top Layer w25: R30.1@2805,2260 C26.2@2805,2330
NetC27_1: C27.1 R34.1 | length 80
  Top Layer w25: C27.1@3570,2400 R34.1@3650,2400
NetC27_2: C27.2 D16.3 U3.7 | length 285
  Top Layer w20: C27.2@3570,2330 3630,2270 U3.7@3630,2234
  Top Layer w25: D16.3@3422.4,2370 3460,2370 3500,2330 C27.2@3570,2330
NetD1_2: D1.2 Q3.2 T1.1 TP3.1 | length 700
  Top Layer w75: TP3.1@2600,3995 D1.2@2600,3835 2679.45,3755.55 T1.1@2679.45,3592.13
  Bottom Layer w75: Q3.2@2400,4150 2555,3995 TP3.1@2600,3995
NetD2_3: D2.3 Q1.1 R4.2 | length 254.3
  Top Layer w35: D2.3@1905,2987.6 2027.6,2987.6 2030,2990 2050,3010 Q1.1@2050,3110
NetD3_1: D3.1 D4.1 D4.3 T1.7 T1.8 T1.9 | length 2301.2
  Top Layer w50: T1.7@3860.55,2607.87 T1.8@3860.55,2804.72 3862.13,2806.3 3862.13,3000 4130,3000 4200,3070 D3.1@4200,3995 4205,4000 D4.1@4205,4250 4205,4320 4225,4340 4390,4340 4405,4325 D4.3@4405,4250
NetD5_2: D5.2 L1.3 | length 574.7
  Bottom Layer w100: D5.2@880,3645 880,3470 945,3405 1175,3405 L1.3@1230,3460
NetD5_3: D5.3 L1.4 | length 564.7
  Bottom Layer w100: L1.4@330,3460 385,3405 605,3405 670,3470 D5.3@670,3645
NetD6_1: D6.1 T1.5 | length 445.4
  Top Layer w35: D6.1@2402.4,3072.6 2509.53,3072.6 2550,3032.13 2550,2934.17 T1.5@2679.45,2804.72
NetD7_3: D7.3 Q2.1 R8.1 | length 193.8
  Top Layer w12: D7.3@2367.6,2890 2372.6,2885 Q2.1@2372.6,2792.4
  Top Layer w35: R8.1@2290,2930 2330,2890 D7.3@2367.6,2890
NetD9_1: D9.1 Q3.1 R10.2 | length 263.6
  Top Layer w20: D9.1@2037.4,4252.4 2122.6,4252.4 2125,4250 Q3.1@2300,4250
NetD9_3: D9.3 R10.1 U1.7 | length 3205
  Top Layer w12: U1.7@2012.7,2279.4 2085.6,2279.4
  Top Layer w20: v1(1825,3390) 1825,3280 1765,3220 1765,2665 1690,2590 1690,2065 1690.3,2065 1725.3,2030 1770,2030 1795,2005 1795,1985 1830,1950 1905,1950 1950,1995 1950,2025 1975,2050 2060,2050 2130,2120 2130,2235 2085.6,2279.4 ; v1(1825,3625) 1825,4002.6 D9.3@2000,4177.6 2122.6,4177.6 R10.1@2125,4180
  Bottom Layer w20: v1(1825,3390) v1(1825,3625)
NetD10_1: D10.1 D11.1 D11.3 T2.7 T2.8 T2.9 | length 2305.6
  Top Layer w75: T2.7@3855.55,677.87 T2.8@3855.55,874.72 ; T2.9@3855.55,1071.57 T2.8@3855.55,874.72 ; D11.3@4095,155 4095,60 4100,55 ; D10.1@4295,410 D11.1@4295,155 4295,55 4100,55 ; T2.8@3855.55,874.72 3749.72,874.72 3730,855 3730,130 3805,55 4100,55
NetD12_2: D12.2 Q5.2 T2.1 TP7.1 | length 2468.8
  Top Layer w25: TP7.1@2610,2055 2610,1945 D12.2@2650,1905
  Top Layer w50: D12.2@2650,1905 2674.45,1880.55 T2.1@2674.45,1662.13
  Top Layer w75: Q5.2@2365,255 2365,365 2405,405 2775,405 2900,530 2900,1625 2865,1660 2775,1660 2676.58,1660 T2.1@2674.45,1662.13
NetD13_1: D13.1 T2.6 | length 1491.2
  Top Layer w35: v1(3820,535) 4010,535 4067.6,592.6 D13.1@4067.6,607.6
  Bottom Layer w35: T2.6@2674.45,677.87 3572.13,677.87 3715,535 v1(3820,535)
NetD13_3: D13.3 R20.1 | length 88
  Top Layer w20: R20.1@4080,760 4105,735 D13.3@4105,682.4
NetD14_1: D14.1 Q5.1 R22.2 | length 258.7
  Top Layer w35: Q5.1@2465,155 2640,155 2642.6,157.6 D14.1@2722.6,157.6
NetD14_3: D14.3 R22.1 U1.10 | length 3843.7
  Top Layer w12: 2189.3,2279.3 U1.10@2231.7,2279.3
  Top Layer w15: 2175,2200 2175,2265 2189.3,2279.3 2190,2279.3
  Top Layer w35: v1(2175,1265) 2175,420 2155,400 1930,400 1890,360 1890,75 1910,55 2810,55 2865,110 2865,205 2837.6,232.4 D14.3@2760,232.4 2752.6,225 R22.1@2640,225 ; v1(2175,1490) 2175,2200
  Bottom Layer w35: v1(2175,1265) v1(2175,1490)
